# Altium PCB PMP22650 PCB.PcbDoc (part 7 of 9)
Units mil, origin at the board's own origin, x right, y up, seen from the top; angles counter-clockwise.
Board outline 11311 x 5233 mil, 8 copper layers (Layer 1, Layer 2, Layer 3, Layer 4, Layer 5, Layer 6, Layer 7, Layer 8), stack 88.6 mil thick; 633 components, 410 nets, 2503 pads, 1993 vias.
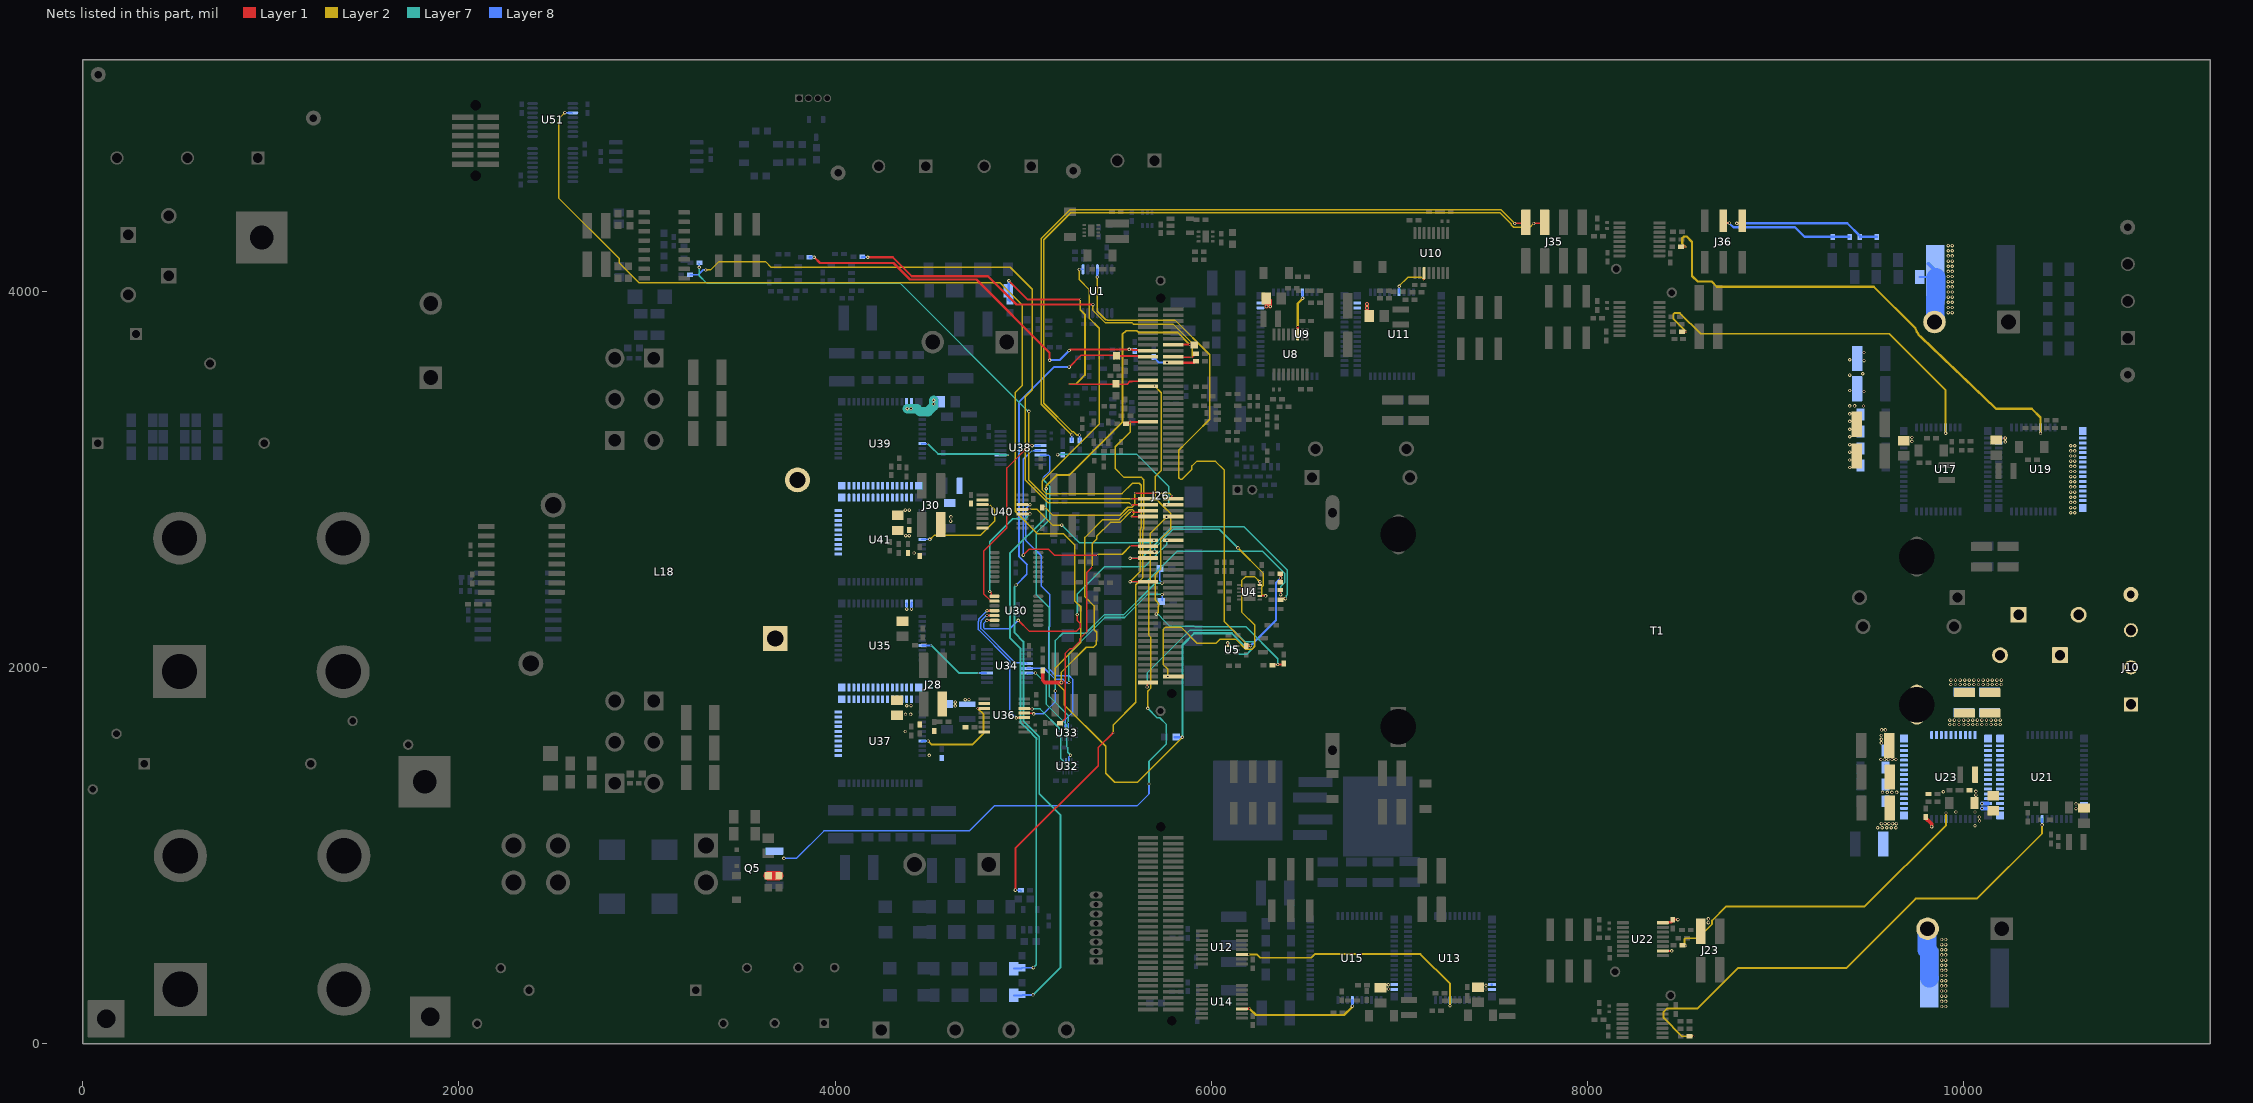
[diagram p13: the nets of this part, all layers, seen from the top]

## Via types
v1: diameter 18, hole 10, Layer 1 to Layer 8, 1759 vias
v2: diameter 8, hole 4, Layer 1 to Layer 2, 160 vias
v3: diameter 18, hole 10, Layer 1 to Layer 8, tented both sides, 34 vias
v4: diameter 8, hole 4, Layer 7 to Layer 8, 28 vias
v5: diameter 19.68, hole 7.87, Layer 1 to Layer 8, 8 vias
v6: diameter 118.11, hole 86.61, Layer 1 to Layer 8, 4 vias

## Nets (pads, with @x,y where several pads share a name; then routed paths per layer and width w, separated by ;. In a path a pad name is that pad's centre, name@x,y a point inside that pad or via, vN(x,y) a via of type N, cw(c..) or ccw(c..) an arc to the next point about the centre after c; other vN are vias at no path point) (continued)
SW_D: C3.1 C5.1 C7.1 C9.1 C119.1 C121.2 C123.1 C124.2 C125.2 J23.1 L10.1 R61.1 U21.1 U21.2 U21.3 U21.4 U21.5 U21.6 U21.7 U21.8 U21.9 U21.10 U21.11 U21.12 U21.13 U21.14 U21.15 U21.16 U22.2 U22.8 U23.17 U23.18 U23.19 U23.20 U23.21 U23.22 U23.23 U23.24 U23.25 U23.26 U23.27 U23.28 U23.29 U23.30 U23.31 U23.32 U23.33 U23.34 U23.35 U23.36 U23.37 U23.38 U23.39 | length 200.3
  Layer 1 w12: U22.8@8400.3,644.5 8402.37,646.57 8446.89,646.57 8457,656.68 C121.2@8457,662 ; U22.2@8401,494 8401.75,494.75 8447.75,494.75 v1(8448,495) ; C121.2@8458,660 8459.31,661.31 8479.69,661.31 v1(8480,661)
  Layer 1 w20: C124.2@9797.27,1205.6 9797.27,1201.66 9829.66,1169.27 v3(9829.66,1155.86)
  other v1: 8642.27,644.83 8642.27,664.85 9925.91,1698.79 9950.32,1698.79 9974.73,1698.79 9999.14,1698.79 10023.56,1698.79 10047.97,1698.79 10072.38,1698.79 10096.79,1698.79 10121.2,1698.79 10145.61,1698.79 10170.02,1698.79 10194.43,1698.79 9925.91,1721.79 9950.32,1721.79 9974.73,1721.79 9999.14,1721.79 10023.56,1721.79 10047.97,1721.79 10072.38,1721.79 10096.79,1721.79 10121.2,1721.79 10145.61,1721.79 10170.02,1721.79 10194.43,1721.79
  other v3: 10060,1160 10084,1186 10083,1207 9958,1233 10060,1233 10064.74,1323.06 9892,1341 10064.74,1343.06
SW_D_RES: C3.2 C5.2 C7.2 C9.2 T1.4
  other v1: 9932.02,1911.1 9956.43,1911.1 9980.85,1911.1 10005.26,1911.1 10029.67,1911.1 10054.08,1911.1 10078.49,1911.1 10102.9,1911.1 10127.31,1911.1 10151.72,1911.1 10176.13,1911.1 10200.55,1911.1 9932.02,1934.1 9956.43,1934.1 9980.85,1934.1 10005.26,1934.1 10029.67,1934.1 10054.08,1934.1 10078.49,1934.1 10102.9,1934.1 10127.31,1934.1 10151.72,1934.1 10176.13,1934.1 10200.55,1934.1
SYSTEM_DISABLE_FET_SUPPLY: J26.85 R18.2 U1.1 | length 3602.1
  Layer 1 w8: v1@5573.27,2457.6 J26.85@5633.27,2457.6 ; R18.2@6366.47,2413.46 6368.27,2411.66 6368,2411.4 v1(6368,2389)
  Layer 2 w8: v1(5298.27,4117.6) 5298.27,4062.6 5352,4008.87 5352,3857 5403.51,3805.49 5403.51,3295.84 5102,2994.33 5102,2945.37 5121.37,2926 5525,2926 5580.5,2981.5 5616.59,2981.5 5627.5,2970.59 5627.5,2743.98 5621,2737.48 5621,2510.87 5573.27,2463.14 v1@5573.27,2457.6
  Layer 7 w8: v1(5568.27,2457.6) 5654.6,2457.6 5817,2620 6132.39,2620 6133.09,2619.3 6148.41,2619.3 6149.12,2620 6271.78,2620 6389,2502.78 6389,2451.79 6368,2430.79 v1(6368,2389)
  Layer 8 w8: v1(5298.27,4117.6) U1.1@5318.27,4117.6
SYSTEM_TEMP_1: C135.1 J26.27 R81.2 | length 2233.1
  Layer 1 w8: J26.27@5633.27,3497.6 v2(5698.27,3497.6) ; R81.2@6324.36,2014.32 6326.11,2016.07 6351.74,2016.07 v1(6353.27,2017.6)
  Layer 1 w12: v1(6353.27,2017.6) 6375.65,2017.6 6378.93,2014.32 6384.74,2020.13 C135.1@6384.74,2023.7
  Layer 2 w8: v2(5698.27,3497.6) 5734,3461.87 5734,3318.03 5734.77,3317.26 5734.77,3152.36 5734,3151.6 5734,3049 5701.5,3016.5 5701.5,2902.34 5744.5,2859.34 5784.77,2819.07 5784.77,2737.77 5730.27,2683.27 5730.27,2522.45 5702.5,2494.68 5702.5,2358.89 5720,2341.39 5720,2328.68 5717.77,2326.44 5717.77,2295.77 v1(5707,2285)
  Layer 7 w8: v1(5707,2285) 5708.77,2283.23 5718.93,2283.23 5734.89,2267.28 5734.89,2264.82 5750.6,2249.1 5779.7,2220 5909.7,2220 5910.6,2219.1 6182.33,2219.1 6353.27,2048.16 v1(6353.27,2017.6)
SYSTEM_WATCHDOG_DISABLE: J26.77 R9.2 | length 1247.3
  Layer 1 w8: v1(5568.27,2582.6) J26.77@5633.27,2582.6
  Layer 1 w12: R9.2@6366.89,2362.6 6372.7,2368.41 6388,2368.41 6388.64,2369.05 6391.82,2369.05 v1(6393.27,2367.6)
  Layer 7 w8: v1(5568.27,2582.6) 5626.76,2582.6 5714.5,2670.34 5714.5,2673.75 5750.75,2710 5751,2710 5792,2751 6172,2751 6404.35,2518.65 6404.35,2388.93 6398.27,2382.85 v1@6398.27,2372.6
SYSTEM_WATCHDOG_OUT: J26.75 U4.7 | length 934.2
  Layer 1 w8: J26.75@5663.41,2615.06 5663.52,2614.95 5691.48,2614.95 J26.75@5691.59,2614.84 ; U4.7@6257.87,2381.91 6258.55,2382.6 v1(6288.27,2382.6)
  Layer 2 w8: v1(6140.75,2637.8) 6277,2501.55 6277,2439 6269,2431 6269,2389.2 6273.69,2384.51 6286.35,2384.51 v1(6288.27,2382.6)
  Layer 7 w8: v1(5698.27,2617.6) 5700.18,2619.51 5700.18,2636.93 5745.5,2682.25 5745.5,2685.66 5756.34,2696.5 5756.59,2696.5 5796.69,2736.6 6041.95,2736.6 v1(6140.75,2637.8)
TEMP_H_A: U10.3 U11.49 | length 233.9
  Layer 1 w8: v2(7131.69,4059.9) 7131.69,4095.69 U10.3@7133,4097
  Layer 2 w8: v1@6998,4028 6998,4029.16 7044.34,4075.5 7117.66,4075.5 7128.5,4064.66 7128.5,4063.5 v2@7131,4061
  Layer 8 w8: U11.49@6999,3992 6998.77,3992.23 6998.77,4027.77 v1(6999,4028)
TEMP_H_B: U14.3 U15.49 | length 650.6
  Layer 1 w12: U14.3@6163.82,187.05 v2@6202.57,187.05
  Layer 2 w12: v2(6204,187) 6204,186.25 6236.75,153.5 6705.49,153.5 6748.85,196.86 v1@6748.85,199.15
  Layer 8 w12: U15.49@6749,233 6749.63,232.37 6749.63,201.37 v1(6750,201)
TEMP_H_C: R212.2 U19.49 | length 2609.9
  Layer 1 w12: R212.2@8495,4238 R212.2@8497.62,4238 v2(8519,4238)
  Layer 2 w12: v2(8519,4238) 8503.5,4253.5 8503.5,4283.83 8513.17,4293.5 8526.83,4293.5 8556,4264.33 8556,4083.41 8585.81,4053.6 8659.85,4053.6 8686.95,4026.5 9521.5,4026.5 9742.11,3805.89 ccw(c9844.57,3838.57) 9770.18,3760.9 10171.09,3377.5 10361.5,3377.5 10408,3331 v1@10408,3247
  Layer 8 w12: U19.49@10407.84,3278.16 10408.34,3277.66 10408.34,3246.66 v1@10410,3245 ; U19.49@10408.34,3277.69 U19.49@10408.68,3278.02
  other v1: 10408,3246
TEMP_H_D: R220.2 U23.49 | length 1816.8
  Layer 1 w10: R220.2@8512,523 v2(8524,523)
  Layer 2 w10: v2@8523,524 8514.5,532.5 8514.5,556.1 8520.4,562 8587.01,562 8661.77,636.76 8661.77,655.76 8737,731 9473.16,731 9906,1163.84 v3(9906,1228)
  Layer 8 w10: U23.49@9903.56,1180.19 9903.56,1192.98 U23.49@9906.43,1195.86 ; v3(9906,1228) 9906.22,1227.78 9906.22,1196.78 U23.49@9908,1195
TEMP_H_PFC_1: U36.3 U37.49 | length 554.7
  Layer 1 w10: v2(4756.52,1784.53) 4796.47,1784.53 U36.3@4797,1784
  Layer 2 w10: v1(4494.12,1610.82) 4494.74,1610.82 4513.56,1592 4730,1592 4789,1651 4789,1752.05 v2(4756.52,1784.53)
  Layer 8 w10: U37.49@4459,1609 4460.64,1610.64 4466.13,1610.64 4493.94,1610.64 v1(4494.12,1610.82) ; U37.49@4463.27,1607.6 U37.49@4466.13,1610.46
TEMP_H_PFC_2: U40.3 U41.49 | length 554.9
  Layer 1 w8: U40.3@4788,2868 4789,2867 v2(4820,2867)
  Layer 2 w8: v1(4503,2683) 4505.16,2683 4525.76,2703.6 4530.71,2703.6 4532.11,2705 4754,2705 4754.5,2705.5 4773.68,2705.5 4848,2779.82 4848,2840 v2@4820,2868
  Layer 7 w8: v1@4510.27,2682.8 v1@4511.07,2681.99
  Layer 8 w8: U41.49@4459,2683 4459.6,2682.4 4494.4,2682.4 v1@4495,2683
TEMP_L_A: U8.3 U9.49 | length 237
  Layer 1 w12: U8.3@6458.98,3772.34 v2@6458.98,3814.57
  Layer 2 w12: v2@6460,3815 6460,3937.01 6479.5,3956.51 6479.5,3957.88 6485,3963.38 v1(6485,3965)
  Layer 8 w12: U9.49@6484,3999 6484.44,3998.56 6484.44,3965.56 v1(6485,3965)
  other v2: 6459.29,3814.57
TEMP_L_B: U12.3 U13.49 | length 1338.5
  Layer 1 w10: U12.3@6162.57,476.05 6163.97,474.64 v2@6199,474.64
  Layer 2 w10: v2(6199,475) 6243.58,475 6260.14,458.44 6531.36,458.44 6550.92,478 7111,478 7269,320 7269,206 v1@7267,204
  Layer 8 w10: U13.49@7268.27,234.6 7269.26,235.59 U13.49@7268.27,236.59 ; v1(7269,203) 7269.13,203.13 7269.13,233.13 U13.49@7270,234
TEMP_L_C: R209.2 U17.49 | length 2025.1
  Layer 1 w10: R209.2@8497,3788 v2(8523,3788)
  Layer 2 w10: v2(8523,3788) 8456,3855 8456,3880.14 8461.86,3886 8491.25,3886 8601.15,3776.1 9602.9,3776.1 9904,3475 9904,3249 v1@9905,3248
  Layer 8 w10: v1(9904,3247) 9903.84,3247.16 9903.84,3277.84 U17.49@9904,3278
TEMP_L_D: R217.2 U21.49 | length 2738.2
  Layer 1 w10: R217.2@8540,40 8541,41 R217.2@8542.62,41 v2(8563,41)
  Layer 2 w10: v2@8562,41 8501.16,41 8404,138.16 8404,170.84 8422.66,189.5 8585.66,189.5 8799.66,403.5 9375.47,403.5 9744.47,772.5 10070.5,772.5 10417,1119 v1(10417,1165)
  Layer 8 w10: v1(10417,1165) 10417.14,1165.14 10417.14,1196.86 U21.49@10417,1197
TEMP_L_PFC_1: U34.3 U35.49 | length 399.2
  Layer 7 w10: v4@4511.98,2118.88 4658.77,1972.1 v4(4761.97,1972.1)
  Layer 8 w10: U35.49@4463.12,2118.88 v4(4510,2118.88) ; v4(4761.97,1972.1) 4802.77,1972.1 U34.3@4803.27,1972.6
TEMP_L_PFC_2: U38.3 U39.49 | length 528.2
  Layer 7 w10: v4@4492.27,3191.6 4492.46,3191.6 4510.62,3173.44 4510.62,3173.25 4547.27,3136.6 4872.31,3136.6 4877.81,3131.1 v4@4916.77,3131.1
  Layer 8 w10: U39.49@4460.27,3190.6 4461.04,3191.37 U39.49@4463.12,3191.37 v4(4492.12,3191.37) ; U38.3@4873.27,3132.6 4874.77,3131.1 U38.3@4878.97,3131.1 v4(4918.97,3131.1)
TTPLPFC_FAULTn: J26.72 U30.6 | length 1506.9
  Layer 1 w8: v1(4807.13,2252.39) 4843.06,2252.39 U30.6@4843.27,2252.6 ; v1(4973.49,2252.39) 5032.89,2193 5281.37,2193 5291.12,2202.74 5304,2215.63 5304,2234.32 5287.06,2251.26 v1(5287.06,2283.25) ; J26.72@5765,2677.6 5823.27,2677.6 J26.72@5818.27,2672.6
  Layer 7 w8: v1(5287.06,2283.25) 5287.06,2392.06 5432,2537 5643.83,2537 5705.93,2599.1 5764,2657.17 v1(5764,2678)
  Layer 8 w8: v1@4804.43,2251.6 4804.43,2251.33 4791.07,2237.98 4791.07,2237.56 4788.77,2235.25 4788.77,2214.28 4795.45,2207.6 4928.7,2207.6 v1(4973.49,2252.39)
TTPLPFC_GAN_FAULT_PH1_H: U30.4 U36.12 | length 748.8
  Layer 1 w8: v1@4964,1734 4964.25,1734.25 5005.05,1734.25 U36.12@5005.3,1734.5 ; U36.12@5008,1732 U36.12@5009.25,1733.25
  Layer 1 w12: v1(4807.13,2303.57) 4842.29,2303.57 U30.4@4843.27,2302.6
  Layer 8 w8: v1@4803.27,2302.42 v1@4803.27,2302.6 ; v1@4804,2302 4804,2301.02 4764.07,2261.1 4764.07,2248.74 4761.77,2246.44 4761.77,2203.1 4928.43,2036.43 4928.43,1768.57 v1(4963,1734)
TTPLPFC_GAN_FAULT_PH1_L: U30.5 U34.12 | length 442.8
  Layer 1 w12: v1(4807.13,2277.98) 4842.88,2277.98 U30.5@4843.27,2277.6
  Layer 8 w8: v1(4807.13,2277.98) 4804.42,2277.98 4799.64,2273.21 4798.21,2273.21 4777.57,2252.57 4777.57,2243.15 4775.27,2240.85 4775.27,2208.69 4957.79,2026.17 5015.5,2026.17 U34.12@5019.57,2022.1
TTPLPFC_GAN_FAULT_PH2_H: U30.1 U40.12 | length 633.1
  Layer 1 w8: v1(4822.13,2405.39) 4822.13,2404.87 4831,2396 ; 4831.03,2396.45 4831.03,2384.83 4835.51,2380.35 U30.1@4847.13,2380.35 ; U40.12@4986,2819 4987.25,2817.75 5035.75,2817.75 v1(5036,2818)
  Layer 7 w8: v1(4822.13,2405.39) 4822.13,2670.13 4944,2792 5010,2792 v1(5036,2818)
TTPLPFC_GAN_FAULT_PH2_L: U30.2 U38.12 | length 1024.7
  Layer 1 w8: U30.2@4847.13,2354.76 4828.05,2354.76 4790,2392.81 4790,2621 4856.23,2687.23 ccw(c4812.26,2736.37) 4861.39,2692.39 4913.5,2744.5 4913.5,3062.83 5033.27,3182.6 v1@5050.9,3182.6
  Layer 8 w8: v1@5048,3181 5048.05,3181.05 5091.52,3181.05 U38.12@5091.57,3181.1
  other v1: 5047,3181
TTPLPFC_GAN_OC_HIGH_FREQ_PH1_H: R93.2 U36.13 | length 1291
  Layer 1 w8: U36.13@5010,1759 5010.25,1758.75 5049.54,1758.75 5053.29,1755 v1(5056,1755) v1@5058,1755
  Layer 7 w8: v1(5170.86,1876.51) 5170.86,2145.19 5209.57,2183.9 5331.97,2183.9 5431.13,2283.06 5534.96,2283.06 5701.7,2449.79 v1(5737.41,2449.79)
  Layer 8 w8: v1(5056,1755) 5106.16,1755 5169,1817.84 5169,1877 v1@5168,1878 ; R93.2@5726.77,2527.6 5726.77,2464.09 5735.49,2455.37 5735.49,2454.41 5737.31,2452.6 v1@5738.27,2452.6
TTPLPFC_GAN_OC_HIGH_FREQ_PH1_L: R92.2 U34.13 | length 1066.7
  Layer 7 w8: v1(5243.08,1921.63) 5243.08,2075.91 5434.55,2267.38 5538.38,2267.38 5660.79,2389.79 v1(5738.41,2389.79)
  Layer 8 w8: U34.13@5019.57,1997.1 5111.09,1997.1 5168.06,1940.13 5210.27,1940.13 5228.77,1921.63 v1(5243.08,1921.63) ; R92.2@5738.41,2357.46 v1(5738.41,2389.79)
TTPLPFC_GAN_OC_HIGH_FREQ_PH2_H: J26.71 U40.13 | length 862.6
  Layer 1 w8: U40.13@4984,2846 4987.25,2842.75 5036.75,2842.75 v2@5037,2843 ; J26.71@5627.02,2678.02 v1(5696,2678)
  Layer 2 w8: v2(5036.04,2842.34) 5072.57,2842.34 5156.07,2758.84 5202.84,2758.84 v1@5204,2760
  Layer 7 w8: v1@5207,2760 5207,2756.64 5299.14,2664.5 5682.5,2664.5 v1(5696,2678)
  other v1: 5204.79,2758.84
TTPLPFC_GAN_OC_HIGH_FREQ_PH2_L: J26.73 U38.13 | length 1292.2
  Layer 1 w8: v1(5000.27,2598.98) 5000.27,2599.37 5031.75,2630.85 5133.15,2630.85 5166,2598 v2(5394,2598) ; v2@5573.27,2647.6 J26.73@5628.27,2647.6
  Layer 2 w8: v2(5394,2598) 5399.5,2603.5 5526,2603.5 v2@5569.25,2646.75
  Layer 8 w8: v1(5000.27,2598.98) 5000.27,3109.27 v4(5046,3155) 5090.47,3155 U38.13@5091.57,3156.1
  other v2: 5569.63,2647.14
TTPLPFC_HIGH_FREQ_PH1_H: J26.61 R106.1 | length 1383.8
  Layer 1 w8: R106.1@5195.56,1703 5222.11,1729.55 5222.11,2075.48 5248.98,2102.35 5261.84,2102.35 5299.05,2139.57 5299.05,2153.17 5336.27,2190.39 5336.27,2505.27 v2(5368,2537) ; v2(5575,2826) 5626.67,2826 J26.61@5633.27,2832.6
  Layer 2 w8: v2(5368,2537) 5367,2538 5367,2660.84 5390,2683.84 5390,2699.43 5463.57,2773 5513.67,2773 5566.67,2826 v2(5575,2826)
TTPLPFC_HIGH_FREQ_PH1_L: J26.63 R101.1 | length 1489.8
  Layer 1 w8: v2(5573.27,2802.6) J26.63@5643.27,2802.6
  Layer 1 w20: R101.1@5103.27,1985.47 5103.57,1985.17 5103.57,1933.35 5115.28,1921.63 v1(5202.61,1921.63)
  Layer 2 w8: v1@5202.61,1916.25 5202.61,1976.94 5334.67,2109 5373,2109 5388.5,2124.5 5388.5,2145.56 5390.27,2147.32 5390.27,2188.78 5376.77,2202.28 5376.77,2329.23 5327.86,2378.14 5327.86,2692.86 5423,2788 5509.58,2788 5561.08,2839.5 5582.31,2839.5 5588.5,2833.31 5588.5,2817.83 v2(5573.27,2802.6)
TTPLPFC_HIGH_FREQ_PH2_H: J26.58 R116.1 | length 855.4
  Layer 1 w8: R116.1@5098,2852 5099.24,2853.24 v2(5115.54,2853.24) ; v2@5594,2927.6 5594.4,2928 v2(5715,2928) ; v2(5788.27,2917.6) 5790.19,2915.68 5790.19,2904.36 5796.95,2897.6 J26.58@5833.27,2897.6
  Layer 2 w8: v2(5115.54,2853.24) 5158.77,2810 5512.49,2810 5555.49,2853 5577.76,2853 5594,2869.24 v2(5594,2927) ; v2(5715,2928) 5777.87,2928 v2(5788.27,2917.6)
TTPLPFC_HIGH_FREQ_PH2_L: J26.60 R111.1 | length 851
  Layer 1 w8: v1(5763,2867) 5816.99,2867.01 J26.60@5818,2866
  Layer 7 w8: v1(5183,3133) 5186.1,3136.1 5601.9,3136.1 5774,2964 5774,2878 v1(5763,2867)
  Layer 8 w8: v1(5183,3133) 5212.87,3133 R111.1@5213.27,3132.6
TTPLPFC_IAC_PH1: C209.1 J26.15 R148.2 | length 2113.8
  Layer 1 w12: v1(3888.27,4182.6) 3918.87,4152 4310,4152 4397.93,4064.07 4751.15,4064.07 5140,3675.22 v1(5140,3635) ; v1(5243.81,3686.63) 5244.89,3686.63 5250.94,3692.67 5578.19,3692.67 5581.1,3689.76 5659.57,3689.76 J26.15@5663.41,3685.92
  Layer 8 w12: R148.2@3863.27,4182.6 3863.78,4182.08 3887.75,4182.08 v1(3888.27,4182.6) ; v1(5140,3635) 5141.63,3636.63 5181,3636.63 ; 5181,3637 5194.18,3637 v1(5243.81,3686.63) ; v1(5563.27,3692.6) 5564.03,3691.83 5587.77,3691.83 5593.27,3686.33 C209.1@5593.27,3682.6
TTPLPFC_IAC_PH2: C203.1 J26.18 R133.2 | length 2169.1
  Layer 1 w8: J26.18@5797.27,3654.43 5799.78,3651.91 v2@5893,3651.91 ; v2@5892,3652 v2(5893,3652) 5900.52,3652 5907.63,3659.11 5907.63,3661.19 5915.44,3669 C203.1@5919.38,3669
  Layer 1 w12: v1(4173.27,4182.6) 4306.4,4182.6 4407.43,4081.57 4813.12,4081.57 4963.69,3931 v1(5371,3931)
  Layer 2 w8: v1@5370,3927 5370,3899.91 5434.91,3835 5578,3835 5585.93,3827.07 5796.43,3827.07 5899.5,3724.01 5899.5,3658.5 v2(5893,3652)
  Layer 8 w12: R133.2@4143.27,4182.6 4144.03,4183.36 4172.5,4183.36 v1(4173.27,4182.6)
TTPLPFC_INRUSH_RELAY: C213.1 J26.64 Q5.1 R156.2 | length 3778.5
  Layer 1 w8: J26.64@5768.27,2802.6 5768.49,2802.82 5796.05,2802.82 J26.64@5797.27,2804.03
  Layer 1 w50: C213.1@3644.27,894.09 R156.2@3700.27,894.09
  Layer 2 w8: v1(5661.77,1784.43) 5661.77,1874.94 5676.77,1889.94 5676.77,2163.25 5666.27,2173.75 5666.27,2447.07 5675,2455.8 5675,2713.42 5762,2800.42 v1(5762,2801)
  Layer 7 w8: v1(5661.77,1784.43) 5711.67,1734.53 5725.34,1734.53 5761.27,1698.6 5761.27,1595.6 5668.47,1502.81 v1(5668.47,1382.15)
  Layer 8 w8: v1@3726.95,987 3794.44,987 3939.94,1132.5 4713.17,1132.5 4846.27,1265.6 5604.75,1265.6 5668.47,1329.32 v1(5668.47,1382.15)
  other v1: 3727,987
TTPLPFC_LOW_FREQ_H: J26.57 R123.1 | length 3123.2
  Layer 1 w8: v2(5573.27,2897.6) J26.57@5628.27,2897.6
  Layer 2 w8: v1(5030,3363) 5028.5,3361.5 5028.5,2999.78 5130.68,2897.6 v2(5573.27,2897.6)
  Layer 7 w8: v1@3277,4129.61 3277,4084 3316,4045 4344,4045 5026,3363 v1(5030,3363)
  Layer 8 w8: R123.1@3275.27,4149.6 3277.51,4147.35 v1@3277.51,4130.56
  other v1: 3277.51,4128.56
TTPLPFC_LOW_FREQ_L: J26.59 R120.1 | length 3618.2
  Layer 1 w8: v2(5573.27,2867.6) J26.59@5633.27,2867.6
  Layer 2 w8: v1(3312,4115) 3337,4115 3382,4160 ; 3383.71,4160 3629,4160 3659.4,4129.6 4930.4,4129.6 5048,4012 5048,3477.63 5011,3440.63 5011,2998.18 5131.18,2878 5562.87,2878 v2(5573.27,2867.6)
  Layer 8 w8: R120.1@3228.89,4089.6 3229.39,4089.1 3271.49,4089.1 3298.4,4116 v1@3316,4116
TTPLPFC_PH1_H_TEMP: U32.2 U36.14 | length 442.2
  Layer 1 w8: U36.14@5012,1784 5013.25,1782.75 5045.25,1782.75 v1(5047,1781)
  Layer 7 w8: v1@5046,1783 5048,1781 5089,1781 5199.77,1670.23 5199.77,1518.23 v4(5227,1491)
  Layer 8 w8: v4(5227,1491) U32.2@5227,1506
TTPLPFC_PH1_L_TEMP: U33.2 U40.14 | length 1406.2
  Layer 1 w8: U40.14@4985,2870 4987.75,2867.25 5035.75,2867.25 v1(5036,2867)
  Layer 8 w8: v1@5033,2866 5033,2865.16 5013.77,2845.93 5013.77,2677.26 5095.68,2595.35 5095.68,2435.44 5140.77,2390.35 5140.77,2220.35 5135.43,2215.01 5135.43,1996.14 5173.72,1957.85 5244.01,1957.85 5264,1937.87 5264,1765.08 5224.3,1725.38 U33.2@5224.3,1685.69
TTPLPFC_PH2_H_TEMP: U33.3 U38.14 | length 1624
  Layer 7 w8: v4(5103.72,3008.93) 5103.72,3002.6 5140,2966.32 5140,2960.16 5140.5,2959.66 5140.5,2788.5 5068,2716 5068,2390.77 5139,2319.77 5139,1889.91 5138.86,1889.76 5138.86,1863.26 5139,1863.11 5139,1847 5238,1748 5238,1711.65 v4(5239.72,1709.93)
  Layer 8 w8: U38.14@5091.52,3131.05 U38.14@5091.57,3131.1 5134.9,3131.1 5142,3124 5142,3047 v4@5104,3009 ; U33.3@5240.05,1685.69 v4@5240.05,1710
TTPLPFC_PH2_L_TEMP: U32.3 U34.14 | length 594.3
  Layer 1 w8: v1(5064.57,1972.1) v1@5066.73,1972.1
  Layer 7 w8: v1(5064.57,1972.1) 5065.73,1972.1 5121.5,1916.33 5121.5,1807.34 5232.5,1696.34 5232.5,1579.43 5236.77,1575.17 5236.77,1550.47 5250,1537.23 v1@5250,1536
  Layer 8 w8: U34.14@5018.27,1967.6 5022.77,1972.1 v1(5064.57,1972.1) ; U32.3@5242.91,1507.97 5242.97,1508.03 5242.97,1526.97 v1(5251,1535)
TTPLPFC_SW1: C161.1 C163.2 C165.1 C166.2 C167.2 J28.1 L13.1 L18.1 R102.1 U35.1 U35.2 U35.3 U35.4 U35.5 U35.6 U35.7 U35.8 U35.9 U35.10 U35.11 U35.12 U35.13 U35.14 U35.15 U35.16 U36.2 U36.8 U37.17 U37.18 U37.19 U37.20 U37.21 U37.22 U37.23 U37.24 U37.25 U37.26 U37.27 U37.28 U37.29 U37.30 U37.31 U37.32 U37.33 U37.34 U37.35 U37.36 U37.37 U37.38 U37.39
  other v1: 4500,1534 4373,1661 4374.04,1752.04 4401.45,1752.04 4638.27,1797.6 4638.27,1817.6 4691.77,1830.97 4711.27,1830.97
TTPLPFC_SW2: C183.1 C185.2 C187.1 C188.2 C189.2 J30.1 L15.1 L18.4 R112.1 U39.1 U39.2 U39.3 U39.4 U39.5 U39.6 U39.7 U39.8 U39.9 U39.10 U39.11 U39.12 U39.13 U39.14 U39.15 U39.16 U40.2 U40.8 U41.17 U41.18 U41.19 U41.20 U41.21 U41.22 U41.23 U41.24 U41.25 U41.26 U41.27 U41.28 U41.29 U41.30 U41.31 U41.32 U41.33 U41.34 U41.35 U41.36 U41.37 U41.38 U41.39
  other v1: 4420,2610 4375,2703 4393.93,2702.6 4614,2780 4615,2802
TTPLPFC_VAC: C202.1 J26.39 R130.2 | length 3095.9
  Layer 1 w10: v1(4958.27,817.6) 4958.27,1040.27 5398.41,1480.41 5398.41,1576.16 5475.25,1653 v2(5479,1653) ; C202.1@5547.85,3296.64 5552.12,3300.91 C202.1@5556.06,3300.91
  Layer 1 w12: C202.1@5546.89,3297.6 C202.1@5552.7,3303.41 ; C202.1@5548.27,3297.6 5554.08,3303.41 5564.08,3303.41 v2(5568.27,3307.6) 5568.82,3307.05 5662.49,3307.05 J26.39@5663.41,3307.97
  Layer 2 w8: v2(5479,1653) 5479,1697.32 5598.5,1816.82 5598.5,2441.92 5634.5,2477.92 5634.5,2731.89 5641,2738.39 5641,3000.18 5629.36,3011.82 5535.95,3011.82 5488.77,3059.01 5488.77,3174.68 5568.27,3254.18 v2(5568.27,3307.6)
  Layer 8 w10: v1(4958.27,817.6) 4958.77,817.1 4983.77,817.1 R130.2@4988.27,812.6
TTPLPFC_VAC_L: C207.1 J26.17 R141.1 R144.1 | length 4252.7
  Layer 1 w10: v1(5243.95,3598.5) 5306.94,3661.49 C207.1@5498.27,3661.49 ; C207.1@5498.27,3657.6 5660.24,3657.6 J26.17@5663.41,3654.43
  Layer 7 w10: v1(4961.92,2440.19) 4961.92,2438.25 4953.99,2430.33 4953.99,2186.01 5000.5,2139.5 5000.5,1717.42 5024.66,1693.26 5085,1632.92 5085,1330 5198.66,1216.34 5198.66,408.15 5052.52,262 v1@5051,262
  Layer 8 w10: R144.1@4949.7,258.6 4993.11,258.6 4994.62,260.1 5050.62,260.1 v1(5051.62,261.1) ; v1(4961.92,2440.19) 5018.77,2497.04 5018.77,2550.23 ; 5020,2549 5018.77,2550.23 ; v1(5243.95,3598.5) 5163.07,3598.5 4978,3413.43 4978,2591 5018.77,2550.23
TTPLPFC_VAC_N: C210.1 J26.14 R147.1 R152.1 | length 4328.4
  Layer 1 w10: J26.14@5818.27,3717.6 5818.67,3718 v2(5885,3718) 5922.87,3718 C210.1@5923.27,3717.6
  Layer 2 w10: v1@5122,2950.22 5122,2969 5177.6,3024.6 5245.27,3024.6 5527,3306.32 5527,3772.14 5546.86,3792 5562.16,3792 5562.26,3792.1 5574.27,3792.1 5574.37,3792 5603.87,3792 5612.87,3783 5820,3783 v2(5885,3718)
  Layer 7 w10: v1(5053.62,406.1) 5069,421.48 5069,1616.95 5069.5,1617.45 5069.5,1626.5 5026,1670 4985,1711 4985,2104 4929,2160 4929,2608 5122,2801 v1(5122,2952)
  Layer 8 w10: R152.1@4949.7,400.6 4990.11,400.6 4994.62,405.1 5052.62,405.1 v1(5053.62,406.1)
TTPLPFC_VBUS: C132.1 J26.20 R74.2 | length 243.2
  Layer 1 w12: v1(5764,3623) J26.20@5797.27,3623 ; J26.20@5797.27,3622.93 5798.26,3621.94 5907.38,3621.94 5915.44,3630 C132.1@5919.38,3630
  Layer 8 w12: R74.2@5693,3651 5693,3648.44 5698.81,3642.63 5701.37,3642.63 5721,3623 v1(5764,3623)
TTPLPFC_VBUS2: C141.1 J26.25 R91.1 R94.2 | length 1475.8
  Layer 1 w8: 5578.27,3522.6 5657.57,3522.6 J26.25@5663.41,3528.44
  Layer 1 w10: v1(4923.27,4057.6) 5023.27,3957.6 v2(5303.27,3957.6) ; v2(5243.27,3507.6) 5552.26,3507.6 5567.26,3522.6 5578.27,3522.6
  Layer 2 w10: v2(5243.27,3507.6) 5278.91,3507.6 5300.99,3529.68 5328,3556.69 5328,3879 5303.27,3903.73 v2(5303.27,3957.6)
  Layer 8 w12: v1@4923.27,4052.6 4923.27,3959.92 4920.35,3957.01 R91.1@4929.27,3948.09
VBATT: F1.1 F2.2 J10.1 J10.2 J10.3 TP3.1
VBATT_F: C18.2 C19.1 C20.2 C21.1 C89.1 C90.1 C91.2 C92.2 C93.1 C94.1 C95.2 C96.2 C111.1 C112.1 C113.2 C114.2 C115.1 C116.1 C117.2 C118.2 F1.2 F2.1 R201.2 U19.1 U19.2 U19.3 U19.4 U19.5 U19.6 U19.7 U19.8 U19.9 U19.10 U19.11 U19.12 U19.13 U19.14 U19.15 U19.16 U23.1 U23.2 U23.3 U23.4 U23.5 U23.6 U23.7 U23.8 U23.9 U23.10 U23.11 U23.12 U23.13 U23.14 U23.15 U23.16 | length 637.6
  Layer 8 w12: R201.2@9765.35,4077.6 C19.1@9853.27,4077.6
  Layer 8 w20: C19.1@9812.81,4147.6 C19.1@9852.02,4108.39
  Layer 8 w100: C18.2@9806.57,599.6 9804.48,597.51 9804.48,500.47 9816.47,488.48 9816.47,351.39 C21.1@9817.26,350.6 ; C20.2@9844.57,3838.57 9848.41,3842.41 9848.41,3964.29 9852.02,3967.91 C19.1@9852.02,4074.6
  other v1: 9882.27,199.29 9903.54,199.29 9882.27,226.7 9903.54,226.7 9882.27,254.11 9903.54,254.11 9882.27,281.52 9903.54,281.52 9882.27,308.92 9903.54,308.92 9882.27,336.33 9903.54,336.33 9882.27,363.74 9903.54,363.74 9882.27,391.15 9903.54,391.15 9882.27,418.56 9903.54,418.56 9882.27,445.97 9903.54,445.97 9882.27,473.37 9903.54,473.37 9882.27,500.78 9903.54,500.78 9882.27,528.19 9903.54,528.19 9882.27,555.6 9903.54,555.6 9542.27,1149.6 9566.52,1149.6 9590.77,1149.6 9615.02,1149.6 9639.27,1149.6 9562.27,1171.6 9582.27,1171.6 9602.27,1171.6 9622.27,1171.6 9642.27,1171.6 9568.27,1337.6 9593.27,1337.6 9618.27,1337.6 9643.27,1337.6 9559.27,1512.6 9579.27,1512.6 9599.27,1512.6 9619.27,1512.6 9639.27,1512.6 9562,1601 9562,1620 9562,1640 9563.27,1669.6 9583.27,1669.6 10569.17,2824.46 10590.44,2824.46 10569.17,2851.87 10590.44,2851.87 10569.17,2879.28 10590.44,2879.28 10569.17,2906.69 10590.44,2906.69 10569.17,2934.09 10590.44,2934.09 10569.17,2961.5 10590.44,2961.5 10569.17,2988.91 10590.44,2988.91 10569.17,3016.32 10590.44,3016.32 10569.17,3043.73 10590.44,3043.73 9394.27,3064.6 10569.17,3071.14 10590.44,3071.14 10569.17,3098.54 10590.44,3098.54 9394.27,3104.49 10569.17,3125.95 10590.44,3125.95 9394.27,3146.48 10569.17,3153.36 10590.44,3153.36 10569.17,3180.77 10590.44,3180.77 9394.27,3186.38 9394.27,3228.37 9394.27,3268.26 9394.27,3310.25 9394.27,3350.15 9394.27,3392.14 9419.7,3392.14 9467,3392 9470.12,3469.02 9394.27,3474.02 9394.27,3555.91 9463,3563 9470.12,3632.8 9394.27,3637.8 9470.12,3676.31 9917.99,3888.29 9939.27,3888.29 9917.99,3915.7 9939.27,3915.7 9917.99,3943.11 9939.27,3943.11 9917.99,3970.52 9939.27,3970.52 9917.99,3997.92 9939.27,3997.92 9917.99,4025.33 9939.27,4025.33 9917.99,4052.74 9939.27,4052.74 9917.99,4080.15 9939.27,4080.15 9917.99,4107.56 9939.27,4107.56 9917.99,4134.97 9939.27,4134.97 9917.99,4162.37 9939.27,4162.37 9917.99,4189.78 9939.27,4189.78 9917.99,4217.19 9939.27,4217.19 9917.99,4244.6 9939.27,4244.6
VDD: J26.118 U4.10 | length 1414.3
  Layer 1 w8: v2(5768.27,1953.78) 5832.22,1953.78 J26.118@5833,1953 ; J26.118@5783.49,1953.64 J26.118@5797.27,1953.64 ; U4.10@6258.27,2442.6 v1(6258.27,2457.6)
  Layer 2 w8: v2(5768.27,1953.78) 5768.27,1993.34 5743.5,2018.1 5743.5,2203.99 5755.6,2216.1 5838.39,2216.1 5924.88,2129.61 6023.6,2129.61 6045.09,2151.1 6130.93,2151.1 6182.93,2099.1 6215.93,2099.1 6231.09,2114.26 6231.09,2226.77 6160.77,2297.1 6160.77,2464.08 6179.69,2483 6231.58,2483 6256.98,2457.6 v1(6258.27,2457.6)
VDDIO: J26.119 U5.1 | length 1017.6
  Layer 1 w8: v1(5658.27,1897.6) 5658.27,1917 J26.119@5663.41,1922.14 ; v1(6087.27,2132.6) 6087.27,2118.6 U5.1@6088.27,2117.6
  Layer 7 w8: v1@5655,1897 5658.27,1900.27 5658.27,1972.43 5862.84,2177 5886.34,2200.5 6116.5,2200.5 6177.78,2139.22 6223.31,2139.22 6228,2134.53 6228,2111.17 6207.3,2090.47 6187.83,2071 6148.87,2071 v1(6087.27,2132.6) ; v1(5658.27,1897.6) v1@5658.27,1898.6
VNEG_H_A: C53.2 U11.40 U11.41 | length 65
  Layer 1 w20: C53.2@6827.27,3868.6 v1(6827.27,3913.6) v1(6827.27,3933.6)
VNEG_H_B: C75.2 U15.40 U15.41
  other v1: 6941,292 6941,315
VNEG_H_C: C97.2 U19.40 U19.41 | length 0.9
  Layer 1 w20: v1@10220.11,3220.94 v1(10221.03,3220.94)
  other v1: 10221.03,3201.08
VNEG_H_D: C119.2 U23.40 U23.41 | length 68
  Layer 8 w20: v3(10097,1252) U23.41@10131,1252 ; v3(10097,1278) U23.40@10131,1278
VNEG_H_PFC_1: C161.2 U37.40 U37.41
  other v1: 4380.44,1798.29 4403,1799
VNEG_H_PFC_2: C183.2 U41.40 U41.41
  other v1: 4372.27,2838.6 4393.93,2838.6
VNEG_L_A: C38.2 U9.40 U9.41 | length 83.9
  Layer 1 w20: C38.2@6292.27,3963.6 6293.15,3962.72 v1(6293.15,3920.6) ; C38.2@6307.27,3958.6 6313,3952.87 6313,3920.87 v1(6313.27,3920.6)
VNEG_L_B: C60.2 U13.40 U13.41 | length 1.7
  Layer 8 w12: U13.40@7490.86,314.74 U13.40@7492.1,315.97
  other v1: 7460,292 7460,312
VNEG_L_C: C82.2 U17.40 U17.41
  other v1: 9724.27,3203.6 9724.27,3224.48
VNEG_L_D: C104.2 U21.40 U21.41
  other v1: 10597.11,1251.01 10597.11,1276.6
VNEG_L_PFC_1: C146.2 U35.40 U35.41 | length 75.1
  Layer 1 w20: C146.2@4354.85,2261.24 C146.2@4361.35,2261.24
  Layer 8 w10: U35.40@4378.27,2342.6 4380.44,2340.43 v1(4380.44,2311.72) ; v1(4406.03,2311.72) U35.41@4406.03,2341.72 4406.03,2345.36 U35.41@4408.27,2347.6
VNEG_L_PFC_2: C168.2 U39.40 U39.41 | length 189.9
  Layer 7 w50: v1(4383.27,3377.6) 4435.65,3377.6 4451.25,3362 4493.98,3362 4523.27,3391.29 v1(4523.27,3422.6)
  other v1: 4403.27,3377.6 4523.27,3402.6
VSNS_INN: J36.3 R205.2 R206.2 | length 711.9
  Layer 1 w10: J36.3@8708.87,4365 8709.87,4364 8710.87,4365 v1@8749,4365
  Layer 8 w12: v1(8754,4365) 8754,4364 8775.5,4342.5 9102.82,4342.5 9154.1,4291.22 R205.2@9303.27,4291.22 ; R205.2@9303.27,4292.6 9304.65,4291.22 R206.2@9393.27,4291.22
VSNS_INP: J36.5 R207.2 R208.2 | length 809.9
  Layer 1 w12: v1(8793,4363) J36.5@8822,4363
  Layer 8 w12: v1(8793,4363) 9380.43,4363 9448.27,4295.16 R207.2@9448.27,4291.22 ; R207.2@9448.27,4287.6 R207.2@9448.27,4291.22 ; R208.2@9538.27,4291.22 R207.2@9448.27,4291.22
VSNS_OUTN: J35.6 R189.1 | length 3907.3
  Layer 1 w8: v1(7713.02,4362.29) 7752.96,4362.29 J35.6@7753.27,4362.6
  Layer 2 w8: v1(5298.27,3237.6) 5284.43,3237.6 5265.93,3256.1 5258.86,3256.1 5108.77,3406.19 5108.77,4275.77 5252,4419 7535,4419 7594.52,4359.48 7594.52,4354.63 7607.28,4341.87 7692.59,4341.87 v1(7713.02,4362.29)
  Layer 8 w8: R189.1@5298.27,3207.6 5299.72,3209.05 5299.72,3236.14 v1(5298.27,3237.6)
VSNS_OUTP: J35.8 R186.1 | length 3792.2
  Layer 1 w8: v1(7613.02,4362.29) 7652.96,4362.29 J35.8@7653.27,4362.6
  Layer 2 w8: v1@5255,3237 5255,3240.86 5095.27,3400.6 5095.27,4282.27 5247,4434 7541.31,4434 v1(7613.02,4362.29)
  Layer 8 w8: R186.1@5258.27,3207.6 5258.12,3207.75 5258.12,3237.45 v1(5258.27,3237.6)
XRSn: R19.2 R24.2 R89.2 R204.2 U1.4 U51.11 | length 11044.8
  Layer 1 w12: R24.2@6185.26,2116.74 6185.69,2117.17 6207.84,2117.17 v1(6208.27,2117.6) ; R204.2@6366.47,2499.84 6368.27,2498.04 v1(6368.27,2477.6) 6367.5,2476.83 6367.5,2453.36 R19.2@6368.27,2452.6
  Layer 2 w8: v1(2563.27,4951.6) 2563.1,4951.6 2529.5,4917.99 2529.5,4497.51 2851.5,4175.51 2851.5,4152.5 2958,4046 4878,4046 4994,3930 4994,3500 4957,3463 4957,2831.82 5075.82,2713 5214.03,2713 5273.86,2653.17 5273.86,2355.77 5305.56,2324.08 5305.56,2135.09 5170,1999.53 5170,1926.93 5216.78,1880.15 5216.78,1804.06 5438.27,1582.57 5438.27,1439.6 5486.87,1391 5606.67,1391 v1(5846.27,1630.6) ; v1(5393.27,4077.6) 5393.27,3895.73 5439,3850 5443.91,3850 5445.41,3848.5 5807.37,3848.5 5991.77,3664.1 5991.77,3321.35 5913.6,3243.18 5867.5,3197.08 5827.07,3156.66 5827.07,3009.93 5835.69,3001.31 5842.31,3001.31 5897,3056 5897,3073.4 5921.1,3097.5 6022.5,3097.5 6068.27,3051.73 6068.27,2245.73 6195.49,2118.51 6207.35,2118.51 v1(6208.27,2117.6)
  Layer 7 w12: v1(5846.27,1630.6) 5846.27,2120.6 5908.67,2183 6107.87,2183 6173.27,2117.6 v1(6208.27,2117.6)
  Layer 8 w8: v1(2563.27,4951.6) 2564.02,4950.85 2600.02,4950.85 U51.11@2603.27,4947.6
  Layer 8 w12: v1(5393.27,4077.6) 5393.85,4078.19 5393.85,4117.01 U1.4@5393.27,4117.6 ; R89.2@5805.27,1630.6 v1(5846.27,1630.6) ; v1(6208.27,2117.6) 6343.27,2252.6 6343.27,2452.6 v1(6368.27,2477.6)
pads on no net: J24.11 J24.MH1 J24.MH2 J25.61 J25.62 J25.121 J25.122 J25.123 J25.124 J25.125 J25.126 J25.127 J25.128 J25.129 J25.130 J25.131 J25.132 J25.133 J25.134 J25.136 J25.137 J25.138 J25.139 J25.140 J25.141 J25.142 J25.143 J25.144 J25.145 J25.146 J25.147 J25.148 J25.149 J25.150 J25.151 J25.152 J25.153 J25.154 J25.155 J25.156 J25.159 J25.160 J25.161 J25.162 J25.163 J25.164 J25.165 J25.166 J25.167 J25.168 J25.169 J25.170 J25.171 J25.172 J25.173 J25.174 J25.175 J25.176 J25.177 J26.1 J26.2 J26.11 J26.12 J26.16 J26.23 J26.24 J26.30 J26.32 J26.40 J26.41 J26.42 J26.43 J26.44 J26.45 J26.46 J26.66 J26.76 J26.78 J26.79 J26.81 J26.82 J26.86 J26.89 J26.92 J26.113 J26.114 J26.115 J26.116 J26.117 J26.181 J26.182 J26.185 J26.186 J36.1 LBL1.0 T2.3 T2.4 T3.1 T3.2 T3.3 T3.4 U1.3 U1.8 U1.11 U3.1 U5.6 U6.2 U6.5 U7.9@5360.87,4306.72 U7.9@5360.87,4342.16 U9.43 U9.47 U9.52 U11.43 U11.47 U11.52 U13.43 U13.47 U13.52 U15.43 U15.47 U15.52 U17.43 U17.47 U17.52 U19.43 U19.47 U19.52 U21.43 U21.47 U21.52 U23.43 U23.47 U23.52 U30.3 U30.11 U32.1 U32.7 U32.8 U33.1 U33.7 U33.8 U35.43 U35.47 U35.52 U37.43 U37.47 U37.52 U39.43 U39.47 U39.52 U41.43 U41.47 U41.52 U42.7 U42.12 U42.13 U45.13 U47.13

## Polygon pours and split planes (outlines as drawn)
PGND on Layer 8 "NONET_L-01_P-001" (solid, remove dead copper, pour order 94): 7173.27,704.6 7563.27,704.6 7563.27,320.21 7518.33,320.21 7518.33,329.6 7490,329.6 7490,108 7173.27,108 7173.27,630.05
TTPLPFC_SW1 on Layer 8 "Layer 8-TTPLPFC_SW1" (solid, remove dead copper, pour order 506): 20 vertices, not listed, extent 3612,1506 4762,2226
SW_B on Layer 8 "NONET_L-01_P-001" (solid, remove dead copper, pour order 89): 6561.27,892.6 6557.57,888.9 6557.57,796.27 6640.58,698.29 6640.58,131 6939.63,131 6939.63,330.6 7008.27,330.6 7008.27,226.6 7148.27,226.6 7148.27,893.6
SW_D on Layer 8 "NONET_L-01_P-001" (solid, remove dead copper, pour order 75): 10225.27,1802.95 10225.27,1188.6 10162.28,1189.18 10162.28,1292.66 10107.8,1292.66 10109.1,1136 9773,1136 9773,1643.73 9938.93,1802.95
SGND on Layer 8 "NONET_L-01_P-001" (solid, remove dead copper, pour order 34): 10003,2804.77 10003,3343 9720.86,3343 9721.14,3176.63 9654.63,3176.63 9628.27,3203 9628.27,3357.6 9628.27,3690.6 9543.27,3690.6 9528.27,3675.6 9528.27,2801.35
SW_C on Layer 8 "Layer 8-SW_C" (solid, pour order 505): 17 vertices, not listed, extent 10016.84,2613 10534,3381
TTPLPFC_SW2 on Layer 8 "NONET_L-01_P-001" (solid, remove dead copper, pour order 128): 3716,3077 3857.71,3077 4014.67,2996.6 4470.27,2996.6 4470.27,2941.37 4461.5,2932.6 4365.27,2932.6 4365.27,2898.9 4365.27,2818 4443,2818 4443,2592.24 3986.25,2592.24 3716,2862.49
DCLINK on Layer 8 "NONET_L-01_P-001" (solid, pour order 471): 6034,315 6034,72 6102,72 6144,114 6144,214 6188,258 6188,315
DCLINK on Layer 8 "NONET_L-01_P-001" (solid, remove dead copper, pour order 156): 3930.27,1181.6 4661.27,1181.6 4725.27,1245.6 4725.27,1330.73 4635,1421 3930.27,1421
SW_A on Layer 8 "NONET_L-01_P-001" (solid, remove dead copper, pour order 120): 6643.04,4005.38 6738.01,4005.38 6738.01,3897.6 6808.27,3897.6 6808.27,4023 6746.59,4023 6746.59,4137.8 7128,4137.8 7128,4018.59 7096,3936.47 7096,3583.15 7159.27,3489.15 7159.27,3398.6 6643.04,3398.6
IPRI_SENSE on Layer 8 "Layer 8-IPRI_SENSE 1" (solid, remove dead copper, pour order 511): 4411,3022.49 4529.93,3022.49 4596.3,3088.86 4596.3,3127 4441.33,3127 4441.33,3349.52 4365.27,3349.52 4365.27,3434.07 4385.58,3454.2 4753.45,3454.2 4753.45,3572.6 3932.27,3572.6 3932.27,3073.6 4411,3073.6
IPRI_SENSE on Layer 8 "Layer 8-IPRI_SENSE" (solid, remove dead copper, pour order 502): 4328.36,1988.91 4580.78,1988.91 4592.92,2001.06 4592.92,2057.5 4564.31,2057.5 4536.8,2030 4436.93,2030 4436.93,2157.04 4436.93,2181.73 4436,2181.73 4436,2367.6 3986.27,2367.6 3986.27,2022.41 4328.36,2022.41
IPRI_SENSE on Layer 8 "NONET_L-01_P-001" (solid, remove dead copper, pour order 193): 4614.27,3444.14 4610.35,3440.22 4610.35,3374.2 4579.28,3374.2 4557.27,3352.2 4557.27,3304.6 4751.52,3304.6 4800.02,3256.1 4840.5,3256.1 4847.25,3249.35 4919.15,3249.35 4919.15,3435.07 4903,3444.14
TTPLPFC_SW2 on Layer 8 "NONET_L-01_P-001" (solid, remove dead copper, pour order 190): 4518.33,2871.86 4518.57,2821.02 4549.65,2789.94 4549.65,2770 4647.2,2768.98 4647.5,2714.13 4551.3,2714.13 4551.3,2672.15 4659.91,2672.15 4742,2754.23 4742,3013 4624.12,3013 4614,3002.88 4614,2916.72 4563.18,2916.72
IPRI_SENSE on Layer 8 "NONET_L-01_P-001" (solid, remove dead copper, pour order 271): 4563.27,2372.6 4758.27,2372.6 4758.27,2327.6 4563.27,2327.6
PGND on Layer 8 "NONET_L-01_P-001" (solid, remove dead copper, pour order 122): 17 vertices, not listed, extent 6121,3254 6587.89,4109.98
VNEG_H_PFC_2 on Layer 8 "NONET_L-01_P-001" (solid, remove dead copper, pour order 184): 4415,2927 4415,2824 4363,2824 4363,2868.66 4371,2871.99 4371,2927
PGND on Layer 8 "NONET_L-01_P-001" (solid, pour order 498): 6297,3096 6297,3038 6282,3023 6282,2994 6330,2946 6384,2946 6384,3026 6356,3026 6337,3045 6337,3108 6309,3108
LC_SW_NODE on Layer 8 "NONET_L-01_P-001" (solid, remove dead copper, pour order 124): 5997.27,1052.6 5998.27,1053.6 5998.27,1591.6 6000.3,1591.6 6126.32,1717.61 6692,1717.61 6692,1460 6483.15,1460 ccw(c6483.15,1350.26) 6378.27,1382.55 6378.27,1060.06 6378.27,1052.6
3V3_PRI on Layer 8 "NONET_L-01_P-001" (solid, remove dead copper, pour order 127): 34 vertices, not listed, extent 5114.09,3743.77 8216,4427.6
NetL13_2 on Layer 8 "NONET_L-01_P-001" (solid, pour order 28): 4440,1811 4440,1779 4435,1774 4421,1774 4416,1779 4416,1811
ISO_12V_H_PFC_2 on Layer 8 "NONET_L-01_P-001" (solid, remove dead copper, pour order 279): 4493.27,2802.6 4493.27,2752.6 4520.28,2752.5 4558.27,2717.6 4637.93,2717.6 4637.93,2761.4 4558.27,2762.6 4518.27,2802.6
PGND on Layer 8 "NONET_L-01_P-001" (solid, remove dead copper, pour order 104): 6206.5,843.6 6206.5,632.13 6189.27,602.13 6046.8,602.13 6011.27,566.6 6011.27,454.6 6055.27,410.6 6189.27,410.6 6189.27,410.04 6237.61,361.7 6237.61,97 6311.67,97 6352.27,137.6 6352.27,843.6
NetL8_2 on Layer 8 "NONET_L-01_P-001" (solid, pour order 496): 10161,3302 10209,3302 10211,3300 10211,3236 10162,3236 10161,3235
ISO_12V_L_D on Layer 8 "NONET_L-01_P-001" (solid, pour order 486): 10511,1263 10543,1263 10543,1223 10511,1223
NetL10_2 on Layer 8 "NONET_L-01_P-001" (solid, pour order 473): 10108,1235 10154,1235 10154,1172 10108,1172
IPRI_SENSE on Layer 8 "NONET_L-01_P-001" (solid, remove dead copper, pour order 288): 4838.27,3918 4838.27,3735 4758,3735 4758,3918
PGND on Layer 8 "NONET_L-01_P-001" (solid, remove dead copper, pour order 172): 2177.27,2138.01 1946,2138.01 1946,2791 2112.94,2791 2112.94,2604.06 2023,2513.63 2023,2288.82 2160.27,2284.6 2177.27,2267.6
AC_L_Sense_1 on Layer 8 "NONET_L-01_P-001" (solid, remove dead copper, pour order 85): 2274.75,2304.6 2586.27,2304.6 2586.27,1829 2274.75,1829
PGND on Layer 8 "NONET_L-01_P-001" (solid, remove dead copper, pour order 225): 5328.14,2652.63 5328.14,2097.64 5331.78,2094 5541.27,2094 5541.27,2652.56
PGND on Layer 8 "NONET_L-01_P-001" (solid, remove dead copper, pour order 260): 5333.27,3917.6 5333.27,3852.6 5353.27,3832.6 5353.27,3747.6 5388.27,3712.6 5643.27,3712.6 5643.27,3832.6 5563.27,3912.6 5538.27,3912.6
DCLINK on Layer 8 "NONET_L-01_P-001" (solid, remove dead copper, pour order 123): 5973.71,3244 5973.71,3546.9 5973.71,3493.27 5782,3684.98 5784.56,3806.51 5973.71,3888.41 5974.47,3934.03 5974.47,4111.14 6143.27,4111.14 6143.27,3244
ISO_12V_H_B on Layer 8 "NONET_L-01_P-001" (solid, remove dead copper, pour order 20): 6828,187 6884,187 6884,134 6828,134
NetL13_2 on Layer 8 "NONET_L-01_P-001" (solid, remove dead copper, pour order 267): 4622,1762.6 4622,1712.6 4748.27,1712.6 4748.27,1762.6
ISO_12V_L_RECT on Layer 8 "NONET_L-01_P-001" (solid, remove dead copper, pour order 298): 2810.27,4379.6 2890.27,4379.6 2890.27,4314.6 2810.27,4314.6
BATT_RTN on Layer 8 "NONET_L-01_P-001" (solid, remove dead copper, pour order 30): 10512,3644.63 11091.17,3644.63 11091.17,4405.2 10782.85,4405.2 10782.85,4259.6 10512,4259.6
SW_C_RES on Layer 8 "NONET_L-01_P-001" (solid, remove dead copper, pour order 32): 9909.23,2591 10330,2591 10330,2449 9910.67,2449
SGND on Layer 8 "NONET_L-01_P-001" (solid, remove dead copper, pour order 33): 10492.27,4272.6 10492.27,3664.56 10472.34,3644.63 10174.27,3644.63 10174.27,4272.6
SW_D_RES on Layer 8 "NONET_L-01_P-001" (solid, remove dead copper, pour order 77): 9704.16,2048.6 10221.72,2048.6 10221.72,1819.6 9929.57,1819.6 9783.64,1691.74 9707.78,1692.61
SW_B_RES on Layer 8 "NONET_L-01_P-001" (solid, remove dead copper, pour order 87): 6557.16,933.6 7127.44,933.6 7127.44,1800.6 6835.26,1800.6 6835.26,1508.42 6698.08,1385.6 6698.08,1173.6 cw(c6493.4,1187.75) 6557.16,992.74
LC_GND on Layer 8 "NONET_L-01_P-001" (solid, remove dead copper, pour order 88): 6431.83,1335.6 6431.83,1166 6643.83,1166 6643.83,1335.6
SW_A_RES on Layer 8 "NONET_L-01_P-001" (solid, remove dead copper, pour order 110): 6711.79,3371.12 7176.27,3371.12 7176.27,3194.6 6711.79,3194.6
VBATT_F on Layer 8 "NONET_L-01_P-001" (solid, remove dead copper, pour order 228): 9799.27,4286.6 9800.27,4285.6 9973.27,4285.6 9973.27,3782.6 9968.27,3777.6 9804.27,3777.6
VBATT_F on Layer 8 "NONET_L-01_P-001" (solid, remove dead copper, pour order 233): 9731.27,679.6 9938.27,679.6 9938.27,177.6 9730.26,177.6
SGND on Layer 8 "NONET_L-01_P-001" (solid, remove dead copper, pour order 236): 10058.27,682.6 10278.27,682.6 10278.27,172.6 10058.27,172.6
LC_GATE on Layer 8 "NONET_L-01_P-001" (solid, remove dead copper, pour order 258): 6463.27,1418 6643.27,1418 6643.27,1343 6463.27,1343
LC_GATE on Layer 8 "NONET_L-01_P-001" (solid, remove dead copper, pour order 259): 6433.5,1162 6433.5,1084 6613.5,1084 6613.5,1162
DCLINK on Layer 8 "NONET_L-01_P-001" (solid, remove dead copper, pour order 300): 5428.27,2042.6 5533.27,2042.6 5533.27,1742.6 5428.27,1742.6
DCLINK on Layer 8 "NONET_L-01_P-001" (solid, remove dead copper, pour order 301): 5855.9,2042.9 6019.27,2042.9 6019.27,1742.9 5855.9,1742.9
DCLINK on Layer 8 "NONET_L-01_P-001" (solid, remove dead copper, pour order 302): 5855.9,2992.9 6012.27,2992.9 6012.27,2692.9 5855.9,2692.9
DCLINK on Layer 8 "NONET_L-01_P-001" (solid, remove dead copper, pour order 304): 5425.9,2992.9 5530.9,2992.9 5530.9,2692.9 5425.9,2692.9
PGND on Layer 8 "NONET_L-01_P-001" (solid, remove dead copper, pour order 305): 5855.9,2652.9 6008.27,2652.9 6008.27,2094 5855.9,2094
SW_A_XFMR on Layer 8 "NONET_L-01_P-001" (solid, remove dead copper, pour order 362): 7053.51,2596.29 7053.51,2946.69 6562.27,2946.69 6562.27,2666.29 6751.54,2666.29 6821.54,2596.29
VBATT on Layer 8 "NONET_L-01_P-001" (solid, remove dead copper, pour order 374): 10446.32,1753.82 11031.66,1753.82 11031.66,2468.32 10446.32,2468.32
SW_C_XFMR on Layer 8 "NONET_L-01_P-001" (solid, remove dead copper, pour order 375): 9522,2739 9525,2742 9834,2742 9834,2448 9837,2445 9836,2444 9525,2444
NetL7_2 on Layer 8 "NONET_L-01_P-001" (solid, pour order 418): 9659.04,3327.38 9702.04,3327.38 9702.04,3239 9659.04,3239
VBATT_F on Layer 8 "NONET_L-01_P-001" (solid, remove dead copper, pour order 69): 10588.92,3294.54 10588.92,3206.81 10551.63,3183.9 10551.63,2810.13 10662.27,2810.13 10662.27,3294.54
VBATT_F on Layer 8 "NONET_L-01_P-001" (solid, remove dead copper, pour order 74): 9524.27,1681 9524.27,986.6 9716.47,986.6 9716.46,1681
NetL9_2 on Layer 8 "NONET_L-01_P-001" (solid, pour order 398): 10619,1236 10619,1113 10670,1113 10671,1114 10671,1236
ISO_12V_L_A on Layer 8 "NONET_L-01_P-001" (solid, pour order 27): 6367,4035 6399,4067 6399,4101 6396,4104 6352,4104 6345,4097 6345,3974 6367,3974
VNEG_L_A on Layer 8 "NONET_L-01_P-001" (solid, remove dead copper, pour order 250): 6237.27,3948.6 6237.27,3903.6 6322.27,3903.6 6322.27,3948.6
AC_N_Re on Layer 8 "NONET_L-01_P-001" (solid, remove dead copper, pour order 167): 1205.27,757.6 2149.27,757.6 2149.27,1148.6 2437.9,1148.6 2437.9,0 1205.27,0
TTPLPFC_INRUSH_RELAY on Layer 8 "NONET_L-01_P-001" (solid, pour order 397): 3613,1052 3738,1052 3738,973 3614.04,973
PGND on Layer 8 "NONET_L-01_P-001" (solid, remove dead copper, pour order 261): 3614,866.5 3731,866.5 3731,785 3614,785
DCLINK on Layer 8 "NONET_L-01_P-001" (solid, remove dead copper, pour order 385): 6042.15,737.77 6042.15,648.36 6185.15,648.36 6185.15,737.77
12V_PRI on Layer 8 "NONET_L-01_P-001" (solid, remove dead copper, pour order 125): 5206,4764 6087,4764 6087,4453.6 5643.56,4453.6 5643.56,4382.55 5472.33,4382.55 5436.64,4320.47 5436.64,4268.83 5287.9,4268.83 5287.9,4229.87 5206,4229.87
VNEG_L_C on Layer 8 "NONET_L-01_P-001" (solid, remove dead copper, pour order 61): 9656.27,3231.38 9728.95,3231.38 9728.95,3190.35 9656.27,3190.35
VNEG_H_C on Layer 8 "NONET_L-01_P-001" (solid, remove dead copper, pour order 64): 10165.59,3227.85 10234.67,3227.85 10234.67,3190.35 10165.59,3190.35
VBATT_F on Layer 8 "NONET_L-01_P-001" (solid, remove dead copper, pour order 68): 9378.27,3693.6 9366.27,3681.6 9366.27,2986.6 9487.12,2986.6 9501.27,3000.74 9501.27,3690.6
SGND on Layer 8 "NONET_L-01_P-001" (solid, remove dead copper, pour order 14): 10675.86,1668.6 10675.86,1288.56 10616,1288.56 10616,1053.77 10306,1053.77 10306,1668.6
SGND on Layer 8 "NONET_L-01_P-001" (solid, remove dead copper, pour order 76): 9505.96,1641.58 9505.96,981.6 9374.27,981.6 9374.27,1641.58
AC_L_F on Layer 8 "NONET_L-01_P-001" (solid, remove dead copper, pour order 78): 44.19,3375.6 294.27,3375.6 294.27,3093.77 44.19,3093.77
AC_N_CON on Layer 8 "NONET_L-01_P-001" (solid, remove dead copper, pour order 79): 676.85,3375.6 1021.27,3375.6 1021.27,3093.77 676.85,3093.77
AC_L on Layer 8 "NONET_L-01_P-001" (solid, remove dead copper, pour order 86): 2277.27,2596.91 2570.27,2596.91 2570.27,2334.6 2277.27,2334.6
DCLINK on Layer 8 "NONET_L-01_P-001" (solid, remove dead copper, pour order 103): 6372.27,844.85 6373.82,367.89 6391.54,342.13 6391.54,97 6445,97 6561.27,213.27 6561.27,769.17 6485.59,844.85
DCLINK on Layer 8 "NONET_L-01_P-001" (solid, remove dead copper, pour order 121): 7154.49,3594.86 7154.49,3959.5 7210.24,4010.76 7262,4010.76 7262,3547 7192.54,3547
12V_SW on Layer 8 "NONET_L-01_P-001" (solid, remove dead copper, pour order 126): 5643.56,4436.23 5643.56,4335.03 5718.27,4335.03 5718.27,4436.23
DCLINK on Layer 8 "NONET_L-01_P-001" (solid, remove dead copper, pour order 132): 3975.84,2527.6 4481.27,2527.6 4481.27,2414.6 3975.84,2414.6
DCLINK on Layer 8 "NONET_L-01_P-001" (solid, remove dead copper, pour order 155): 3948.27,3753.6 3948.27,3611 4735,3611 4735,3717.18 4692,3750.41 4692,3903.41 4605.45,3903.41 4558.27,3950.6 4558.27,4219.5 4458.35,4219.5 4151.45,3912.6 4151.45,3808.78 4096.27,3753.6
IPRI_SENSE on Layer 8 "NONET_L-01_P-001" (solid, remove dead copper, pour order 157): 3925.27,1146.6 4713.27,1146.6 4713.27,842.6 4593.27,842.6 4593.27,1012.6 4512.46,1012.6 4497.46,1027.6 4150.13,1027.6 4150.13,878.46 4088.27,816.6 3924.16,816.6
DCLINK on Layer 8 "NONET_L-01_P-001" (solid, remove dead copper, pour order 160): 4152.63,1012.6 4540.27,1012.6 4573.27,979.6 4573.27,829.6 4191.73,829.6 4152.63,868.7
3V3_PRI on Layer 8 "NONET_L-01_P-001" (solid, remove dead copper, pour order 183): 2218,2524.72 2218,2431.87 2056.25,2431.87 2035.68,2452.44 2035.68,2524.72
NetL15_2 on Layer 8 "NONET_L-01_P-001" (solid, remove dead copper, pour order 191): 4600.22,3010.66 4600.22,2916.72 4540.1,2916.72 4498.91,2875.53 4439.03,2875.53 4439.03,2914.7 4456.93,2932.6 4486.24,2932.6 4564.31,3010.66
AC_N on Layer 8 "NONET_L-01_P-001" (solid, remove dead copper, pour order 197): 2475.27,1225.6 2478.27,1228.6 3166.27,1228.6 3166.27,979.3 3112.57,925.6 2479.27,925.6
AC_N_Re on Layer 8 "NONET_L-01_P-001" (solid, remove dead copper, pour order 198): 2404.27,1135.6 2110.27,1135.6 2110.27,710.6 2332.27,488.6 3114.27,488.6 3195.27,569.6 3195.27,800.6 3127.27,868.6 2687.22,868.6 2553.84,735.22 2475.27,735.22 2475.27,737.56 2409.8,803.03
PGND on Layer 8 "NONET_L-01_P-001" (solid, remove dead copper, pour order 202): 3060.72,4168.6 3174,4168.6 3174,4201 3282,4201 3282,4309 3221.86,4309 3186.46,4273.6 3060.72,4273.6
PGND on Layer 8 "NONET_L-01_P-001" (solid, remove dead copper, pour order 211): 4847.25,3908.18 4979.27,3908.18 4979.27,3836.42 4998.64,3817.04 5155.77,3817.04 5155.77,3802.05 5140.82,3787.1 5099.03,3787.1 5099.03,3750.51 5167.44,3750.51 5166.97,3667.6 4847.25,3667.6
3V3_PRI on Layer 8 "NONET_L-01_P-001" (solid, remove dead copper, pour order 215): 5329.77,3916.03 5329.77,3849.3 5330.38,3849.3 5343.26,3836.42 5342.81,3835.98 5342.81,3806 5334.72,3806 5212.22,3683.5 5165.71,3683.5 5165.71,3741 5252.85,3828.14 5278.54,3828.14 5278.54,3901.29 5300.47,3916.03
3V3_PRI on Layer 8 "NONET_L-01_P-001" (solid, remove dead copper, pour order 216): 5147.88,2900.92 5189.33,2900.92 5189.33,2802.97 5185.26,2798.9 5144.29,2798.9 5144.29,2900.92
IPRI_SENSE on Layer 8 "NONET_L-01_P-001" (solid, remove dead copper, pour order 224): 5278.01,2636.52 5278.19,2104.75 5184.93,2104.75 5184.93,2636.52
12V_PRI on Layer 8 "NONET_L-01_P-001" (solid, remove dead copper, pour order 226): 5693.27,1348.6 5698.35,1353.68 5738.27,1353.68 5738.27,1286.77 5730.34,1278.84 5693.27,1278.84
12V_PRI on Layer 8 "NONET_L-01_P-001" (solid, remove dead copper, pour order 227): 4868.38,1239.6 4873.47,1244.68 4913.38,1244.68 4913.38,1177.77 4905.46,1169.84 4868.38,1169.84
VNEG_L_D on Layer 8 "NONET_L-01_P-001" (solid, remove dead copper, pour order 230): 10670,1288.56 10584.99,1288.56 10584.99,1240.92 10670,1240.92
VNEG_H_A on Layer 8 "NONET_L-01_P-001" (solid, remove dead copper, pour order 237): 6837.27,3948.6 6837.27,3903.6 6752.27,3903.6 6752.27,3948.6
NetL4_2 on Layer 8 "NONET_L-01_P-001" (solid, remove dead copper, pour order 238): 6830,4002 6830,3953.6 6753,3953.6 6753,4002
ISO_12V_H_A on Layer 8 "NONET_L-01_P-001" (solid, remove dead copper, pour order 25): 6943,4104 6943,4056.99 6886.68,4056.99 6886.68,4104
